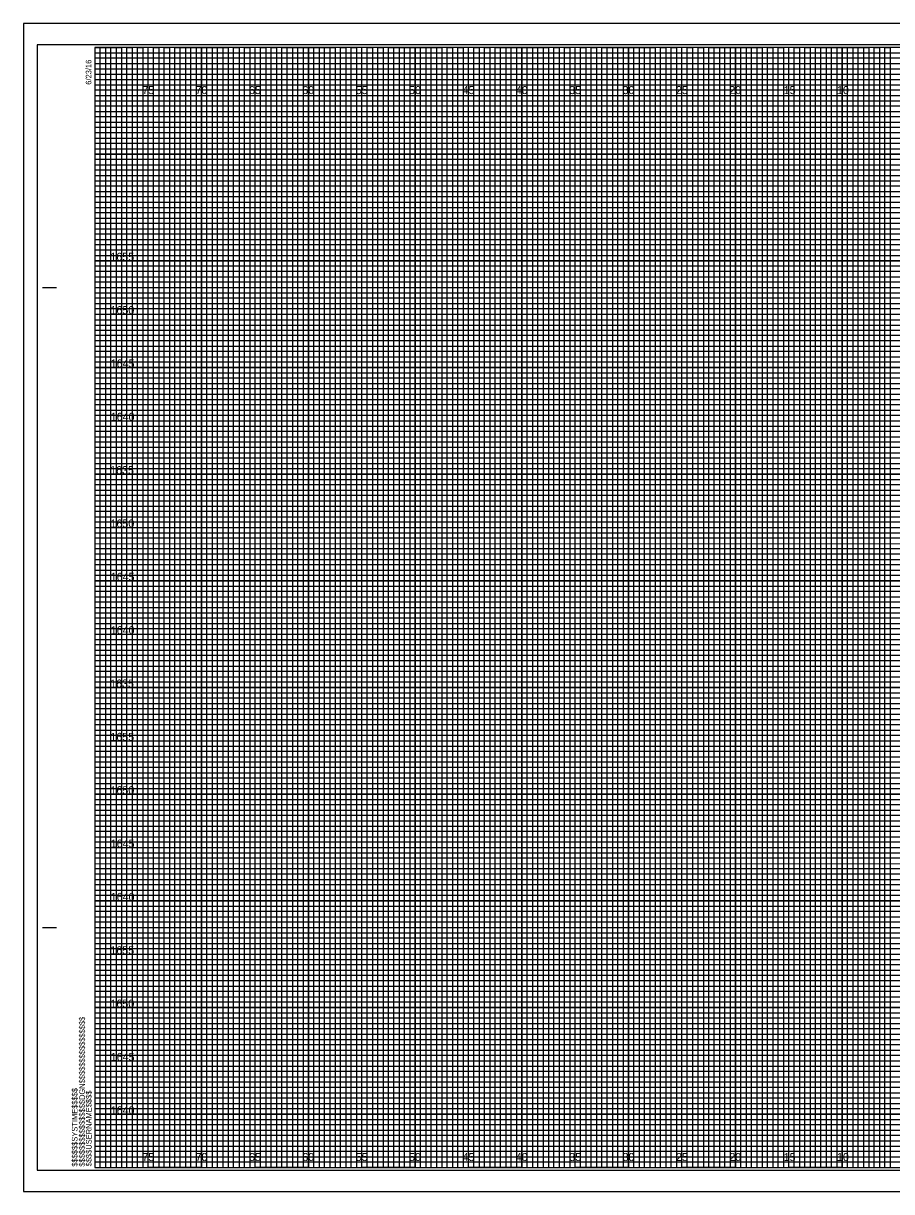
# Model space of a CAD drawing. Extents: x -7 to 162, y -2 to 107.
# Drawn here: x -6.7 to 74.6, y -2.3 to 107.3 of the extents above; entities that cross this region are included whole.
import ezdxf

# ---------------------------------------------------------------- set-up
doc = ezdxf.new("R2010")
doc.units = 0
for name, color, linetype in [('Prop Grid Mask', 7, 'Continuous'), ('Prop XS Elevation Labels', 7, 'Continuous'), ('Sheet Cross Section CELL', 7, 'Continuous'), ('Sheet Cross Section Grid Major CELL', 7, 'Continuous'), ('Sheet Cross Section Grid Middle CELL', 7, 'Continuous'), ('Sheet Cross Section Grid Minor 1 CELL', 7, 'Continuous'), ('Sheet Cross Section Grid Minor 2 CELL', 7, 'Continuous'), ('Sheet Cutting Line CELL', 7, 'Continuous'), ('Sheet DOT Grid CELL', 7, 'Continuous'), ('Sheet Plot Border Inside CELL', 7, 'Continuous'), ('Sheet Plot Border Outside CELL', 7, 'Continuous')]:
    doc.layers.add(name, color=color, linetype=linetype)

msp = doc.modelspace()

# ---------------------------------------------------------------- linework, layer by layer
at = {"layer": 'Sheet Cross Section CELL'}
for p, q in [((-4.9, 82.5), (-3.65, 82.5)), ((-4.85, 82.5), (-3.6, 82.5)), ((-4.9, 22.5), (-3.65, 22.5)), ((-4.85, 22.5), (-3.6, 22.5)), ((0, 0), (0, 0)), ((0, 0), (0, 0)), ((0, 0), (0, 0)), ((0, 0), (0, 0)), ((0, 0), (0, 0)), ((0, 0), (0, 0)), ((0, 0), (0, 0))]:
    msp.add_line(p, q, dxfattribs=at)
msp.add_lwpolyline([(160, 105), (0, 105), (0, 0), (160, 0)], close=True, dxfattribs=at)
at = {"layer": 'Sheet Cross Section Grid Major CELL'}
for p, q in [((5, 105), (0, 105)), ((5, 0), (5, 105)), ((15, 105), (10, 105)), ((10, 105), (10, 0)), ((15, 0), (15, 105)), ((25, 105), (20, 105)), ((20, 105), (20, 0)), ((25, 0), (25, 105)), ((35, 105), (30, 105)), ((30, 105), (30, 0)), ((35, 0), (35, 105)), ((45, 105), (40, 105)), ((40, 105), (40, 0)), ((45, 0), (45, 105)), ((55, 105), (50, 105)), ((50, 105), (50, 0)), ((55, 0), (55, 105)), ((65, 105), (60, 105)), ((60, 105), (60, 0)), ((65, 0), (65, 105)), ((75, 105), (70, 105)), ((70, 105), (70, 0)), ((10, 0), (5, 0)), ((20, 0), (15, 0)), ((30, 0), (25, 0)), ((40, 0), (35, 0)), ((50, 0), (45, 0)), ((60, 0), (55, 0)), ((70, 0), (65, 0))]:
    msp.add_line(p, q, dxfattribs=at)
for points in [[(0, 100), (160, 100), (160, 95), (0, 95)], [(0, 90), (160, 90), (160, 85), (0, 85)], [(0, 80), (160, 80), (160, 75), (0, 75)], [(0, 70), (160, 70), (160, 65), (0, 65)], [(0, 60), (160, 60), (160, 55), (0, 55)], [(0, 50), (160, 50), (160, 45), (0, 45)], [(0, 40), (160, 40), (160, 35), (0, 35)], [(0, 30), (160, 30), (160, 25), (0, 25)], [(0, 20), (160, 20), (160, 15), (0, 15)], [(0, 10), (160, 10), (160, 5), (0, 5)]]:
    msp.add_lwpolyline(points, dxfattribs=at)
at = {"layer": 'Sheet Cross Section Grid Middle CELL'}
for points in [[(0, 105), (2.5, 105), (2.5, 0), (7.5, 0), (7.5, 105), (12.5, 105), (12.5, 0), (17.5, 0), (17.5, 105), (22.5, 105), (22.5, 0), (27.5, 0), (27.5, 105), (32.5, 105), (32.5, 0), (37.5, 0), (37.5, 105), (42.5, 105), (42.5, 0), (47.5, 0), (47.5, 105), (52.5, 105), (52.5, 0), (57.5, 0), (57.5, 105), (62.5, 105), (62.5, 0), (67.5, 0), (67.5, 105), (72.5, 105), (72.5, 0), (77.5, 0)], [(0, 102.5), (137.5, 102.5)], [(0, 92.5), (160, 92.5), (160, 97.5), (0, 97.5)], [(0, 82.5), (160, 82.5), (160, 87.5), (0, 87.5)], [(0, 72.5), (160, 72.5), (160, 77.5), (0, 77.5)], [(0, 62.5), (160, 62.5), (160, 67.5), (0, 67.5)], [(0, 52.5), (160, 52.5), (160, 57.5), (0, 57.5)], [(0, 42.5), (160, 42.5), (160, 47.5), (0, 47.5)], [(0, 32.5), (160, 32.5), (160, 37.5), (0, 37.5)], [(0, 22.5), (160, 22.5), (160, 27.5), (0, 27.5)], [(0, 12.5), (160, 12.5), (160, 17.5), (0, 17.5)], [(0, 2.5), (160, 2.5), (160, 7.5), (0, 7.5)]]:
    msp.add_lwpolyline(points, dxfattribs=at)
at = {"layer": 'Sheet Cross Section Grid Minor 1 CELL'}
for p, q in [((0, 104.5), (130, 104.5)), ((130, 103.99), (0, 103.99)), ((0, 103.99), (0, 103.5)), ((0, 103.5), (130, 103.5)), ((130, 102.95), (0, 102.95)), ((0, 102.95), (0, 102)), ((0, 102), (160, 102))]:
    msp.add_line(p, q, dxfattribs=at)
for points in [[(0, 101.5), (135, 101.5), (160, 101.5), (160, 101), (0, 101)], [(0, 100.5), (160, 100.5), (160, 99.5), (0, 99.5)], [(0, 99), (160, 99), (160, 98.5), (0, 98.49)], [(0, 98), (160, 98), (160, 97), (0, 97)], [(0, 96.5), (160, 96.5), (160, 96), (0, 96)], [(0, 95.5), (160, 95.5), (160, 94.5), (0, 94.5)], [(0, 94), (160, 94), (160, 93.5), (0, 93.5)], [(0, 93), (160, 93), (160, 92), (0, 92)], [(0, 91.5), (160, 91.5), (160, 91), (0, 91)], [(0, 90.5), (160, 90.5), (160, 89.5), (0, 89.5)], [(0, 89), (160, 89), (160, 88.5), (0, 88.5)], [(0, 88), (160, 88), (160, 86.98), (160, 86.5), (160, 86), (0, 86)], [(0, 87), (160, 87), (160, 86.5), (0, 86.5)], [(0, 85.5), (160, 85.5), (160, 84.5), (0, 84.52)], [(0, 84.52), (160, 84.5), (160, 84), (0, 84)], [(0, 83.5), (160, 83.5), (160, 83), (0, 83)], [(0, 82), (160, 82), (160, 81.5), (0, 81.5)], [(0, 81), (160, 81), (160, 80.5), (0, 80.5)], [(-0.04, 79.45), (160, 79.45), (160, 78.94), (-0.04, 78.94)], [(0, 78.5), (160, 78.5), (160, 78), (0, 78)], [(0, 77), (160, 77), (160, 76.5), (0, 76.5)], [(0, 76), (160, 76), (160, 75.5), (0, 75.5)], [(0, 74.5), (160, 74.5), (160, 74), (0, 74)], [(0, 73.5), (160, 73.5), (160, 73), (0, 73)], [(0, 72), (160, 72), (160, 71.5), (0, 71.5)], [(0, 71), (160, 71), (160, 70.5), (0, 70.5)], [(0, 69.5), (160, 69.5), (160, 68.99), (0, 69)], [(0, 68.5), (160, 68.5), (160, 68), (0, 68)], [(0, 67), (160, 67), (160, 66.5), (0, 66.5)], [(0, 66), (160, 66), (160, 65.5), (0, 65.5)], [(0, 64.5), (160, 64.5), (160, 64), (0, 64)], [(0, 63.5), (160, 63.5), (160, 63), (0, 63)], [(0, 62), (160, 62), (160, 61.5), (0, 61.5)], [(0, 61), (160, 61), (160, 60.5), (0, 60.5)], [(0, 59.5), (160, 59.5), (160, 59), (0, 59)], [(0, 58.5), (160.03, 58.45), (160, 58), (0, 58)], [(0, 57), (160, 57), (160, 56.5), (0, 56.5)], [(0, 56), (160, 56), (160, 55.5), (0, 55.5)], [(0, 54.5), (160, 54.5), (160, 54), (0, 54)], [(0, 53.5), (160, 53.5), (160, 53), (0, 53)], [(0, 52), (160, 52), (160, 51.5), (0, 51.5)], [(0, 51), (160, 51), (160, 50.5), (0, 50.5)], [(0, 49.5), (160, 49.5), (160, 49), (0, 49)], [(0, 48.5), (160, 48.5), (160, 48), (0, 48)], [(0, 47), (160, 47), (160, 46.5), (0, 46.5)], [(0, 46), (160, 46), (160, 45.5), (0, 45.5)], [(0, 44.5), (160, 44.5), (160, 44), (0, 44)], [(0, 43.5), (160, 43.5), (160, 43), (0, 43)], [(0, 42), (160, 42), (160, 41.5), (0, 41.5)], [(0, 41), (160, 41), (160, 40.5), (0, 40.5)], [(0, 39.5), (160, 39.5), (160, 38.99), (0, 39)], [(0, 38.5), (160, 38.5), (160, 38), (0, 38)], [(0, 37), (160, 37), (160, 36.5), (0, 36.5)], [(0, 36), (160, 36), (160, 35.5), (0, 35.5)], [(0, 34.5), (160, 34.5), (160, 34), (0, 34)], [(0, 33.5), (160, 33.5), (160, 33), (0, 33)], [(0, 32), (160, 32), (160, 31.5), (0, 31.5)], [(0, 31), (160, 31), (160, 30.5), (0, 30.5)], [(0, 29.5), (160, 29.5), (160, 29), (0, 29)], [(0, 28.5), (160.03, 28.46), (160, 28), (0, 28)], [(0, 27), (160, 27), (160, 26.5), (0, 26.5)], [(0, 26), (160, 26), (160, 25.5), (0, 25.5)], [(0, 24.5), (160, 24.5), (160, 24), (0, 24)], [(0, 23.5), (160, 23.5), (160, 23), (0, 23)], [(0, 22), (160, 22), (160, 21.5), (0, 21.5)], [(0, 21), (160, 21), (160, 20.5), (0, 20.5)], [(0, 19.5), (160, 19.5), (160, 19), (0, 19)], [(0, 18.5), (160, 18.5), (160, 18), (0, 18)], [(0, 17), (160, 17), (160, 16.5), (0, 16.5)], [(0, 16), (160, 16), (160, 15.5), (0, 15.5)], [(0, 14.5), (160, 14.5), (160, 14), (0, 14)], [(0, 13.5), (160, 13.5), (160, 13), (0, 13)], [(0, 12), (160, 12), (160, 11.5), (0, 11.5)], [(0, 11), (160, 11), (160, 10.5), (0, 10.5)], [(0, 9.5), (160, 9.5), (160, 9), (0, 9)], [(0, 8.5), (160, 8.5), (160, 8), (0, 8)], [(0, 7), (160, 7), (160, 6.5), (0, 6.5)], [(0, 6), (160, 6), (160, 5.5), (0, 5.5)], [(0, 4.5), (160, 4.5), (160, 4), (0, 4)], [(0, 3.5), (160, 3.5), (160, 3), (0, 3)], [(0, 2), (160, 2), (160, 1.5), (0, 1.5)], [(0, 1), (160, 1), (160, 0.5), (0, 0.5)]]:
    msp.add_lwpolyline(points, dxfattribs=at)
at = {"layer": 'Sheet Cross Section Grid Minor 2 CELL'}
for points in [[(0, 0), (0.5, 0), (0.5, 105), (1, 105), (1, 0)], [(1, 0), (1.5, 0), (1.5, 105), (2, 105), (2, 0)], [(2.5, 0), (3, 0), (3, 105), (3.5, 105), (3.5, 0)], [(3.5, 0), (4, 0), (4, 105), (4.5, 105), (4.5, 0)], [(5, 0), (5.5, 0), (5.5, 105), (6, 105), (6, 0)], [(6, 0), (6.5, 0), (6.5, 105), (7, 105), (7, 0)], [(7.5, 0), (8, 0), (8, 105), (8.5, 105), (8.5, 0)], [(8.5, 0), (9, 0), (9, 105), (9.5, 105), (9.5, 0)], [(10, 0), (10.5, 0), (10.5, 105), (11, 105), (11, 0)], [(11, 0), (11.5, 0), (11.5, 105), (12, 105), (12, 0)], [(12.5, 0), (13, 0), (13, 105), (13.5, 105), (13.5, 0)], [(13.5, 0), (14, 0), (14, 105), (14.5, 105), (14.5, 0)], [(15, 0), (15.5, 0), (15.5, 105), (16, 105), (16, 0)], [(16, 0), (16.5, 0), (16.5, 105), (17, 105), (17, 0)], [(17.5, 0), (18, 0), (18, 105), (18.5, 105), (18.5, 0)], [(18.5, 0), (19, 0), (19, 105), (19.5, 105), (19.5, 0)], [(20, 0), (20.5, 0), (20.5, 105), (21, 105), (21, 0)], [(21, 0), (21.5, 0), (21.5, 105), (22, 105), (22, 0)], [(22.5, 0), (23, 0), (23, 105), (23.5, 105), (23.5, 0)], [(23.5, 0), (24, 0), (24, 105), (24.5, 105), (24.5, 0)], [(25, 0), (25.5, 0), (25.5, 105), (26, 105), (26, 0)], [(26, 0), (26.5, 0), (26.5, 105), (27, 105), (27, 0)], [(27.5, 0), (28, 0), (28, 105), (28.5, 105), (28.5, 0)], [(28.5, 0), (29, 0), (29, 105), (29.5, 105), (29.5, 0)], [(30, 0), (30.5, 0), (30.5, 105), (31, 105), (31, 0)], [(31, 0), (31.5, 0), (31.5, 105), (32, 105), (32, 0)], [(32.5, 0), (33, 0), (33, 105), (33.5, 105), (33.5, 0)], [(33.5, 0), (34, 0), (34, 105), (34.5, 105), (34.5, 0)], [(35, 0), (35.5, 0), (35.5, 105), (36, 105), (36, 0)], [(36, 0), (36.5, 0), (36.5, 105), (37, 105), (37, 0)], [(37.5, 0), (38, 0), (38, 105), (38.5, 105), (38.5, 0)], [(38.5, 0), (39, 0), (39, 105), (39.5, 105), (39.5, 0)], [(40, 0), (40.5, 0), (40.5, 105), (41, 105), (41, 0)], [(41, 0), (41.5, 0), (41.5, 105), (42, 105), (42, 0)], [(42.5, 0), (43, 0), (43, 105), (43.5, 105), (43.5, 0)], [(43.5, 0), (44, 0), (44, 105), (44.5, 105), (44.5, 0)], [(45, 0), (45.5, 0), (45.5, 105), (46, 105), (46, 0)], [(46, 0), (46.5, 0), (46.5, 105), (47, 105), (47, 0)], [(47.5, 0), (48, 0), (48, 105), (48.5, 105), (48.5, 0)], [(48.5, 0), (49, 0), (49, 105), (49.5, 105), (49.5, 0)], [(50, 0), (50.5, 0), (50.5, 105), (51, 105), (51, 0)], [(51, 0), (51.5, 0), (51.5, 105), (52, 105), (52, 0)], [(52.5, 0), (53, 0), (53, 105), (53.5, 105), (53.5, 0)], [(53.5, 0), (54, 0), (54, 105), (54.5, 105), (54.5, 0)], [(55, 0), (55.5, 0), (55.5, 105), (56, 105), (56, 0)], [(56, 0), (56.5, 0), (56.5, 105), (57, 105), (57, 0)], [(57.5, 0), (58, 0), (58, 105), (58.5, 105), (58.5, 0)], [(58.5, 0), (59, 0), (59, 105), (59.5, 105), (59.5, 0)], [(60, 0), (60.5, 0), (60.5, 105), (61, 105), (61, 0)], [(61, 0), (61.5, 0), (61.5, 105), (62, 105), (62, 0)], [(62.5, 0), (63, 0), (63, 105), (63.5, 105), (63.5, 0)], [(63.5, 0), (64, 0), (64, 105), (64.5, 105), (64.5, 0)], [(65, 0), (65.5, 0), (65.5, 105), (66, 105), (66, 0)], [(66, 0), (66.5, 0), (66.5, 105), (67, 105), (67, 0)], [(67.5, 0), (68, 0), (68, 105), (68.5, 105), (68.5, 0)], [(68.5, 0), (69, 0), (69, 105), (69.5, 105), (69.5, 0)], [(70, 0), (70.5, 0), (70.5, 105), (71, 105), (71, 0)], [(71, 0), (71.5, 0), (71.5, 105), (72, 105), (72, 0)], [(72.5, 0), (73, 0), (73, 105), (73.5, 105), (73.5, 0)], [(73.5, 0), (74, 0), (74, 105), (74.5, 105), (74.5, 0)]]:
    msp.add_lwpolyline(points, dxfattribs=at)
at = {"layer": 'Sheet Cutting Line CELL'}
for p, q in [((161.65, 107.25), (-6.7, 107.25)), ((-6.7, 107.25), (-6.7, -2.25)), ((-6.7, -2.25), (161.65, -2.25))]:
    msp.add_line(p, q, dxfattribs=at)
at = {"layer": 'Sheet DOT Grid CELL'}
for p, q in [((5, 0), (5, 105)), ((10, 0), (10, 105)), ((15, 0), (15, 105)), ((20, 0), (20, 105)), ((25, 0), (25, 105)), ((30, 0), (30, 105)), ((35, 0), (35, 105)), ((40, 0), (40, 105)), ((45, 0), (45, 105)), ((50, 0), (50, 105)), ((55, 0), (55, 105)), ((60, 0), (60, 105)), ((65, 0), (65, 105)), ((70, 0), (70, 105)), ((0, 100), (160, 100)), ((0, 95), (160, 95)), ((0, 90), (160, 90)), ((0, 85), (160, 85)), ((0, 80), (160, 80)), ((0, 75), (160, 75)), ((0, 70), (160, 70)), ((0, 65), (160, 65)), ((0, 60), (160, 60)), ((0, 55), (160, 55)), ((0, 50), (160, 50)), ((0, 45), (160, 45)), ((0, 40), (160, 40)), ((0, 35), (160, 35)), ((0, 30), (160, 30)), ((0, 25), (160, 25)), ((0, 20), (160, 20)), ((0, 15), (160, 15)), ((0, 10), (160, 10)), ((0, 5), (160, 5))]:
    msp.add_line(p, q, dxfattribs=at)
at = {"layer": 'Sheet Plot Border Inside CELL'}
msp.add_lwpolyline([(-5.4, -0.25), (161.2, -0.25), (161.2, 105.25), (-5.4, 105.25)], close=True, dxfattribs=at)
at = {"layer": 'Sheet Plot Border Outside CELL'}
msp.add_lwpolyline([(-6.7, -2.25), (161.65, -2.25), (161.65, 107.25), (-6.7, 107.25)], close=True, dxfattribs=at)

# ---------------------------------------------------------------- texts
at = {"layer": 'Prop Grid Mask'}
for s, p in [('75', (4.44, 100.62)), ('75', (4.44, 100.62)), ('70', (9.43, 100.62)), ('70', (9.43, 100.62)), ('65', (14.44, 100.62)), ('65', (14.44, 100.62)), ('60', (19.43, 100.62)), ('60', (19.43, 100.62)), ('55', (24.44, 100.62)), ('55', (24.44, 100.62)), ('50', (29.43, 100.62)), ('50', (29.43, 100.62)), ('45', (34.44, 100.62)), ('45', (34.44, 100.62)), ('40', (39.43, 100.62)), ('40', (39.43, 100.62)), ('35', (44.44, 100.62)), ('35', (44.44, 100.62)), ('30', (49.43, 100.62)), ('30', (49.43, 100.62)), ('25', (54.44, 100.62)), ('25', (54.44, 100.62)), ('20', (59.43, 100.62)), ('20', (59.43, 100.62)), ('15', (64.53, 100.62)), ('15', (64.53, 100.62)), ('10', (69.52, 100.62)), ('10', (69.52, 100.62)), ('75', (4.44, 0.62)), ('75', (4.44, 0.62)), ('70', (9.43, 0.62)), ('70', (9.43, 0.62)), ('65', (14.44, 0.62)), ('65', (14.44, 0.62)), ('60', (19.43, 0.62)), ('60', (19.43, 0.62)), ('55', (24.44, 0.62)), ('55', (24.44, 0.62)), ('50', (29.43, 0.62)), ('50', (29.43, 0.62)), ('45', (34.44, 0.62)), ('45', (34.44, 0.62)), ('40', (39.43, 0.62)), ('40', (39.43, 0.62)), ('35', (44.44, 0.62)), ('35', (44.44, 0.62)), ('30', (49.43, 0.62)), ('30', (49.43, 0.62)), ('25', (54.44, 0.62)), ('25', (54.44, 0.62)), ('20', (59.43, 0.62)), ('20', (59.43, 0.62)), ('15', (64.53, 0.62)), ('15', (64.53, 0.62)), ('10', (69.52, 0.62)), ('10', (69.52, 0.62))]:
    msp.add_text(s, height=0.75, dxfattribs=at).set_placement(p)
at = {"layer": 'Prop XS Elevation Labels'}
for s, p in [('1655', (1.45, 85)), ('1655', (1.45, 85)), ('1650', (1.46, 80)), ('1650', (1.46, 80)), ('1645', (1.48, 75)), ('1645', (1.48, 75)), ('1640', (1.48, 70)), ('1640', (1.48, 70)), ('1635', (1.43, 65)), ('1635', (1.43, 65)), ('1650', (1.46, 60)), ('1650', (1.46, 60)), ('1645', (1.48, 55)), ('1645', (1.48, 55)), ('1640', (1.48, 50)), ('1640', (1.48, 50)), ('1635', (1.43, 45)), ('1635', (1.43, 45)), ('1655', (1.45, 40)), ('1655', (1.45, 40)), ('1650', (1.46, 35)), ('1650', (1.46, 35)), ('1645', (1.48, 30)), ('1645', (1.48, 30)), ('1640', (1.48, 25)), ('1640', (1.48, 25)), ('1655', (1.45, 20)), ('1655', (1.45, 20)), ('1650', (1.46, 15)), ('1650', (1.46, 15)), ('1645', (1.48, 10)), ('1645', (1.48, 10)), ('1640', (1.48, 5)), ('1640', (1.48, 5))]:
    msp.add_text(s, height=0.75, dxfattribs=at).set_placement(p)
at = {"layer": 'Sheet Cross Section CELL'}
for s, p in [('6/23/16', (-0.33, 101.5)), ('$$$$$$$$$$$$$$$$DGN$$$$$$$$$$$$$$$$', (-0.94, 0.09)), ('$$$$$$SYSTIME$$$$$', (-1.63, 0.09)), ('$$$$USERNAME$$$$', (-0.31, 0.12))]:
    msp.add_text(s, height=0.525, rotation=90, dxfattribs=at).set_placement(p)

doc.saveas('drawing.dxf')
